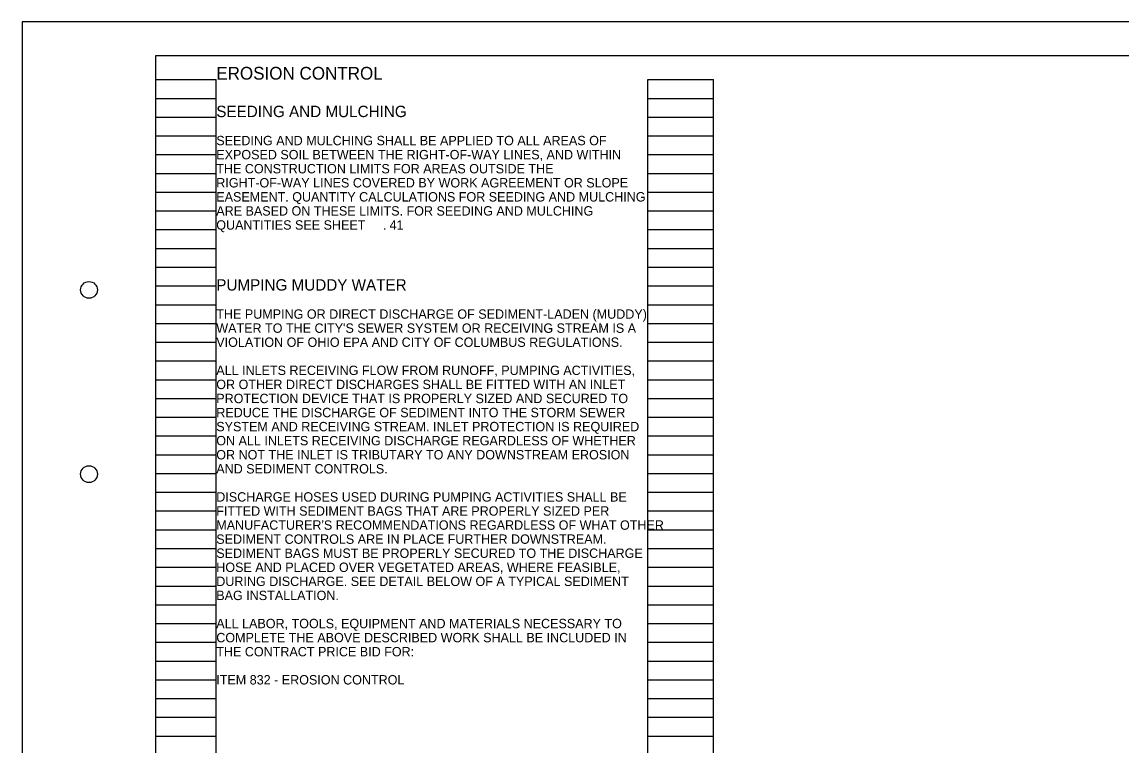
# Model space of a CAD drawing. Extents: x 0 to 34, y 0 to 22.
# Drawn here: x 0 to 16.42, y 11.21 to 22 of the extents above; entities that cross this region are included whole.
import ezdxf

# ---------------------------------------------------------------- set-up
doc = ezdxf.new("R2010")
doc.units = 0
for name, color, linetype in [('SC_Scratch1', 7, 'Continuous'), ('SH_Border', 7, 'Continuous'), ('SH_Cut_Line', 7, 'Continuous'), ('SH_Text', 7, 'Continuous'), ('TX_P_1', 7, 'Continuous')]:
    doc.layers.add(name, color=color, linetype=linetype)

msp = doc.modelspace()

# ---------------------------------------------------------------- linework, layer by layer
at = {"layer": 'SC_Scratch1'}
for p, q in [((2, 0.98), (2, 21.14)), ((2, 21.14), (2.9, 21.14)), ((2.9, 0.98), (2.9, 21.14)), ((9.34, 0.98), (9.34, 21.14)), ((9.34, 21.14), (10.32, 21.14)), ((10.32, 0.98), (10.32, 21.14)), ((2, 20.86), (2.9, 20.86)), ((9.34, 20.86), (10.32, 20.86)), ((2, 20.58), (2.9, 20.58)), ((9.34, 20.58), (10.32, 20.58)), ((2, 20.3), (2.9, 20.3)), ((9.34, 20.3), (10.32, 20.3)), ((2, 20.02), (2.9, 20.02)), ((9.34, 20.02), (10.32, 20.02)), ((2, 19.74), (2.9, 19.74)), ((9.34, 19.74), (10.32, 19.74)), ((2, 19.46), (2.9, 19.46)), ((9.34, 19.46), (10.32, 19.46)), ((2, 19.18), (2.9, 19.18)), ((9.34, 19.18), (10.32, 19.18)), ((2, 18.9), (2.9, 18.9)), ((9.34, 18.9), (10.32, 18.9)), ((2, 18.62), (2.9, 18.62)), ((9.34, 18.62), (10.32, 18.62)), ((2, 18.34), (2.9, 18.34)), ((9.34, 18.34), (10.32, 18.34)), ((2, 18.06), (2.9, 18.06)), ((9.34, 18.06), (10.32, 18.06)), ((2, 17.78), (2.9, 17.78)), ((9.34, 17.78), (10.32, 17.78)), ((2, 17.5), (2.9, 17.5)), ((9.34, 17.5), (10.32, 17.5)), ((2, 17.22), (2.9, 17.22)), ((9.34, 17.22), (10.32, 17.22)), ((2, 16.94), (2.9, 16.94)), ((9.34, 16.94), (10.32, 16.94)), ((2, 16.66), (2.9, 16.66)), ((9.34, 16.66), (10.32, 16.66)), ((2, 16.38), (2.9, 16.38)), ((9.34, 16.38), (10.32, 16.38)), ((2, 16.1), (2.9, 16.1)), ((9.34, 16.1), (10.32, 16.1)), ((2, 15.82), (2.9, 15.82)), ((9.34, 15.82), (10.32, 15.82)), ((2, 15.54), (2.9, 15.54)), ((9.34, 15.54), (10.32, 15.54)), ((2, 15.26), (2.9, 15.26)), ((9.34, 15.26), (10.32, 15.26)), ((2, 14.98), (2.9, 14.98)), ((9.34, 14.98), (10.32, 14.98)), ((2, 14.7), (2.9, 14.7)), ((9.34, 14.7), (10.32, 14.7)), ((2, 14.42), (2.9, 14.42)), ((9.34, 14.42), (10.32, 14.42)), ((2, 14.14), (2.9, 14.14)), ((9.34, 14.14), (10.32, 14.14)), ((2, 13.86), (2.9, 13.86)), ((9.34, 13.86), (10.32, 13.86)), ((2, 13.58), (2.9, 13.58)), ((9.34, 13.58), (10.32, 13.58)), ((2, 13.3), (2.9, 13.3)), ((9.34, 13.3), (10.32, 13.3)), ((2, 13.02), (2.9, 13.02)), ((9.34, 13.02), (10.32, 13.02)), ((2, 12.74), (2.9, 12.74)), ((9.34, 12.74), (10.32, 12.74)), ((2, 12.46), (2.9, 12.46)), ((9.34, 12.46), (10.32, 12.46)), ((2, 12.18), (2.9, 12.18)), ((9.34, 12.18), (10.32, 12.18)), ((2, 11.9), (2.9, 11.9)), ((9.34, 11.9), (10.32, 11.9)), ((2, 11.62), (2.9, 11.62)), ((9.34, 11.62), (10.32, 11.62)), ((2, 11.34), (2.9, 11.34)), ((9.34, 11.34), (10.32, 11.34))]:
    msp.add_line(p, q, dxfattribs=at)
at = {"layer": 'SH_Border'}
msp.add_lwpolyline([(2, 21.5), (33.5, 21.5), (33.5, 0.5), (2, 0.5)], close=True, dxfattribs=at)
for centre in [(1, 18), (1, 15.25)]:
    msp.add_circle(centre, 0.125, dxfattribs=at)
at = {"layer": 'SH_Cut_Line'}
msp.add_lwpolyline([(0, 0), (34, 0), (34, 22), (0, 22)], close=True, dxfattribs=at)

# ---------------------------------------------------------------- texts
at = {"layer": 'SH_Text'}
for s, p in [('SEEDING AND MULCHING SHALL BE APPLIED TO ALL AREAS OF ', (2.9, 20.16)), ('EXPOSED SOIL BETWEEN THE RIGHT-OF-WAY LINES, AND WITHIN ', (2.9, 19.95)), ('THE CONSTRUCTION LIMITS FOR AREAS OUTSIDE THE ', (2.9, 19.74)), ('RIGHT-OF-WAY LINES COVERED BY WORK AGREEMENT OR SLOPE ', (2.9, 19.53)), ('EASEMENT. QUANTITY CALCULATIONS FOR SEEDING AND MULCHING ', (2.9, 19.32)), ('ARE BASED ON THESE LIMITS. FOR SEEDING AND MULCHING ', (2.9, 19.11)), ('QUANTITIES SEE SHEET     .', (2.9, 18.9)), ('41', (5.487, 18.9)), ('THE PUMPING OR DIRECT DISCHARGE OF SEDIMENT-LADEN (MUDDY) ', (2.9, 17.57)), ("WATER TO THE CITY'S SEWER SYSTEM OR RECEIVING STREAM IS A ", (2.9, 17.36)), ('VIOLATION OF OHIO EPA AND CITY OF COLUMBUS REGULATIONS.', (2.9, 17.15)), ('ALL INLETS RECEIVING FLOW FROM RUNOFF, PUMPING ACTIVITIES, ', (2.9, 16.73)), ('OR OTHER DIRECT DISCHARGES SHALL BE FITTED WITH AN INLET ', (2.9, 16.52)), ('PROTECTION DEVICE THAT IS PROPERLY SIZED AND SECURED TO ', (2.9, 16.31)), ('REDUCE THE DISCHARGE OF SEDIMENT INTO THE STORM SEWER ', (2.9, 16.1)), ('SYSTEM AND RECEIVING STREAM. INLET PROTECTION IS REQUIRED ', (2.9, 15.89)), ('ON ALL INLETS RECEIVING DISCHARGE REGARDLESS OF WHETHER ', (2.9, 15.68)), ('OR NOT THE INLET IS TRIBUTARY TO ANY DOWNSTREAM EROSION ', (2.9, 15.47)), ('AND SEDIMENT CONTROLS. ', (2.9, 15.26)), ('DISCHARGE HOSES USED DURING PUMPING ACTIVITIES SHALL BE ', (2.9, 14.84)), ('FITTED WITH SEDIMENT BAGS THAT ARE PROPERLY SIZED PER ', (2.9, 14.63)), ("MANUFACTURER'S RECOMMENDATIONS REGARDLESS OF WHAT OTHER ", (2.9, 14.42)), ('SEDIMENT CONTROLS ARE IN PLACE FURTHER DOWNSTREAM. ', (2.9, 14.21)), ('SEDIMENT BAGS MUST BE PROPERLY SECURED TO THE DISCHARGE ', (2.9, 14)), ('HOSE AND PLACED OVER VEGETATED AREAS, WHERE FEASIBLE, ', (2.9, 13.79)), ('DURING DISCHARGE. SEE DETAIL BELOW OF A TYPICAL SEDIMENT ', (2.9, 13.58)), ('BAG INSTALLATION.', (2.9, 13.37)), ('ALL LABOR, TOOLS, EQUIPMENT AND MATERIALS NECESSARY TO ', (2.9, 12.95)), ('COMPLETE THE ABOVE DESCRIBED WORK SHALL BE INCLUDED IN ', (2.9, 12.74)), ('THE CONTRACT PRICE BID FOR:', (2.9, 12.53)), ('ITEM 832 - EROSION CONTROL', (2.9, 12.11))]:
    msp.add_text(s, height=0.14, dxfattribs=at).set_placement(p)
at = {"layer": 'TX_P_1'}
for s, height, p in [('EROSION CONTROL', 0.19, (2.9, 21.14)), ('SEEDING AND MULCHING', 0.17, (2.9, 20.58)), ('PUMPING MUDDY WATER', 0.17, (2.9, 17.99))]:
    msp.add_text(s, height=height, dxfattribs=at).set_placement(p)

doc.saveas('drawing.dxf')
